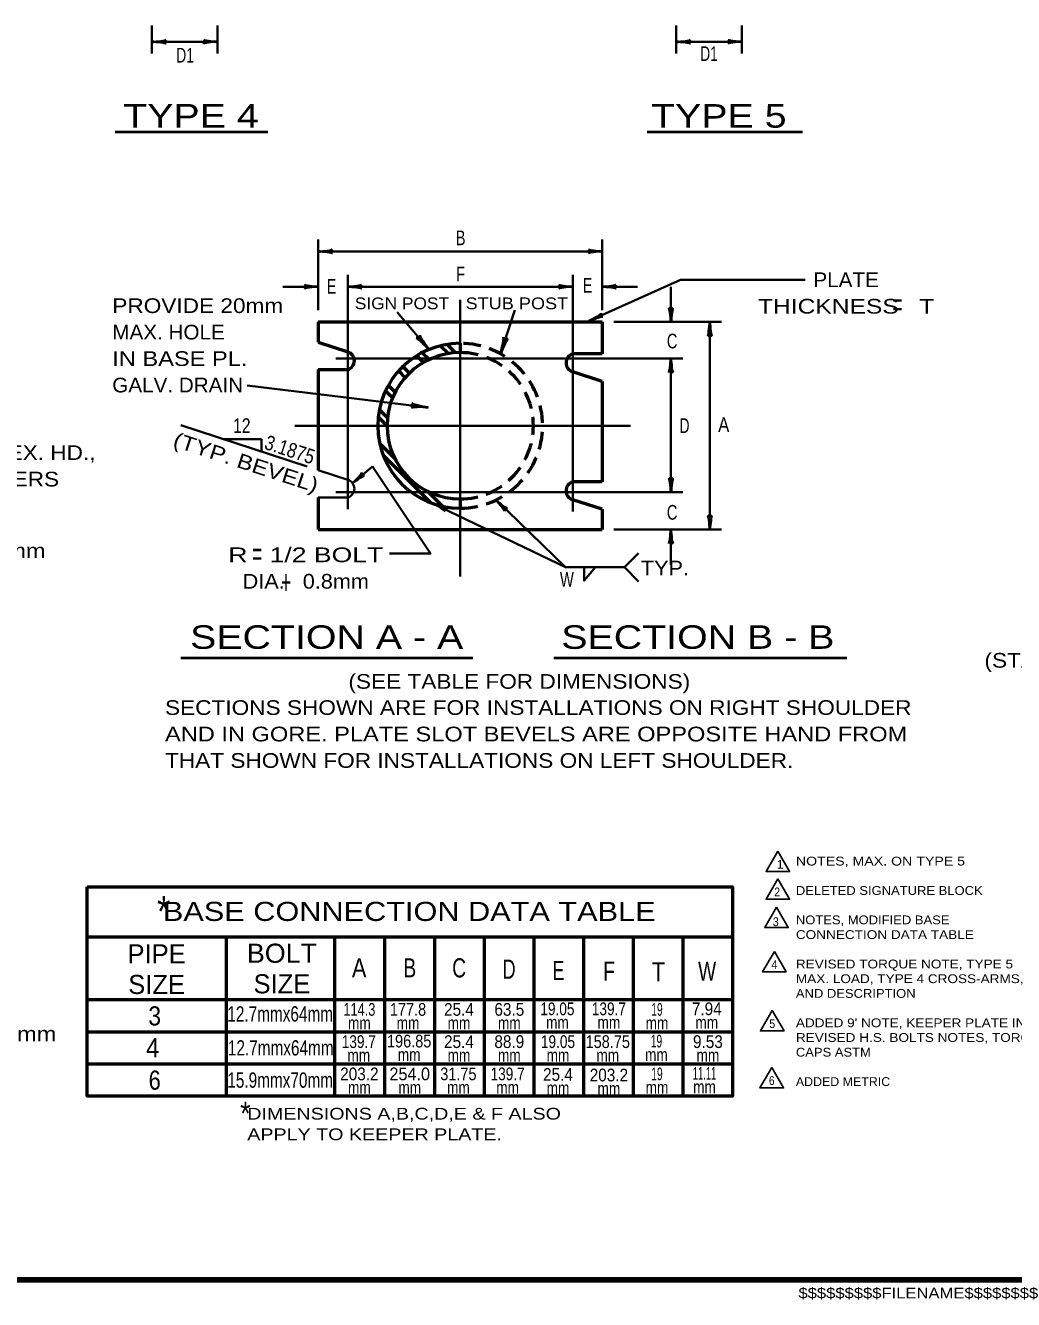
# Model space of a CAD drawing. Extents: x 11 to 867, y -284 to 260.
# Drawn here: x 429.3 to 630.9, y -276.1 to -16.1 of the extents above; entities that cross this region are included whole.
import ezdxf
from ezdxf.enums import TextEntityAlignment as Align

# ---------------------------------------------------------------- set-up
doc = ezdxf.new("R2010")
doc.units = 0
doc.header["$LTSCALE"] = 1.2
doc.linetypes.add('MEDIUM_DASHED', pattern=[4.5, 3, -1.5])
doc.layers.add('1', color=7, linetype='Continuous', lineweight=53)

msp = doc.modelspace()

# ---------------------------------------------------------------- linework, layer by layer
at = {"layer": '1', "lineweight": 35}
for p, q in [((455.129, -16.126), (455.129, -21.85)), ((468.493, -16.126), (468.493, -21.85)), ((562.089, -16.126), (562.089, -21.85)), ((575.453, -16.126), (575.453, -21.85)), ((455.129, -19.45), (468.493, -19.45)), ((562.089, -19.45), (575.453, -19.45)), ((489.053, -74.235), (489.053, -59.835)), ((489.053, -62.235), (546.969, -62.235)), ((546.969, -74.235), (546.969, -59.835)), ((495.059, -67.035), (495.059, -114.865)), ((540.963, -67.035), (540.963, -115.303)), ((489.053, -69.435), (481.853, -69.435)), ((495.059, -69.435), (540.963, -69.435)), ((544.347, -76.403), (562.932, -68.008)), ((546.969, -69.435), (554.169, -69.435)), ((560.995, -76.635), (560.995, -69.435)), ((562.932, -68.008), (588.379, -68.008)), ((518.011, -72.1), (518.011, -80.99)), ((511.632, -82.246), (505.183, -74.636)), ((526.246, -83.144), (529.131, -74.233)), ((549.369, -76.635), (571.331, -76.635)), ((568.931, -76.635), (568.931, -118.985)), ((518.011, -82.881), (518.011, -112.738)), ((492.659, -84.073), (563.395, -84.073)), ((560.995, -84.073), (560.995, -111.367)), ((511.477, -94.083), (474.575, -89.585)), ((461.003, -97.706), (486.771, -106.125)), ((484.253, -97.809), (552.737, -97.809)), ((496.073, -109.555), (500.099, -106.095)), ((489.053, -106.867), (495.059, -108.831)), ((492.659, -111.367), (563.395, -111.367)), ((489.053, -112.465), (495.059, -112.465)), ((518.011, -114.629), (518.011, -128.585)), ((549.369, -118.985), (571.331, -118.985)), ((560.995, -118.985), (560.995, -126.185)), ((551.509, -126.693), (554.407, -129.591))]:
    msp.add_line(p, q, dxfattribs=at)
at = {"layer": '1', "lineweight": 40}
for p, q in [((447.655, -37.837), (478.743, -37.837)), ((556.154, -37.837), (587.864, -37.837)), ((461.03, -145.139), (520.582, -145.139)), ((537.136, -145.139), (596.878, -145.139))]:
    msp.add_line(p, q, dxfattribs=at)
at = {"layer": '1'}
for p, q in [((489.053, -76.635), (546.969, -76.635)), ((489.053, -76.635), (489.053, -80.755)), ((546.969, -76.635), (546.969, -83.155)), ((489.053, -80.755), (495.059, -82.717)), ((511.66, -84.312), (510.247, -82.899)), ((515.531, -83.092), (513.94, -81.501)), ((517.055, -82.919), (515.35, -81.214)), ((518.011, -80.99), (518.011, -82.881)), ((546.969, -83.155), (540.963, -83.155)), ((507.644, -87.084), (506.306, -85.746)), ((510.546, -84.895), (509.165, -83.514)), ((489.053, -86.351), (495.059, -86.351)), ((489.053, -86.351), (489.053, -106.867)), ((506.815, -87.952), (505.476, -86.613)), ((546.969, -88.751), (540.963, -86.789)), ((504.212, -92.137), (502.779, -90.704)), ((504.749, -90.978), (503.354, -89.583)), ((546.969, -88.751), (546.969, -109.269)), ((503.094, -97.807), (501.296, -96.01)), ((503.178, -96.195), (501.524, -94.54)), ((504.66, -104.465), (501.577, -101.382)), ((512.014, -113.516), (502.294, -103.796)), ((514.432, -114.237), (511.354, -111.159)), ((546.969, -109.269), (540.963, -109.269)), ((489.053, -112.465), (489.053, -118.985)), ((518.011, -112.738), (518.011, -114.629)), ((546.969, -114.865), (540.963, -112.903)), ((546.969, -114.865), (546.969, -118.985)), ((489.053, -118.985), (546.969, -118.985)), ((470.311, -234.638), (470.311, -202.19)), ((502.601, -202.19), (502.601, -234.638)), ((512.736, -202.19), (512.736, -234.638)), ((522.873, -202.19), (522.873, -234.638)), ((533.008, -202.19), (533.008, -234.638)), ((543.145, -202.19), (543.145, -234.638)), ((553.28, -202.19), (553.28, -234.638)), ((563.415, -202.19), (563.415, -234.638)), ((573.55, -214.982), (441.919, -214.982)), ((573.55, -221.534), (441.919, -221.534)), ((573.55, -228.086), (441.919, -228.086))]:
    msp.add_line(p, q, dxfattribs=at)
at = {"layer": '1', "lineweight": 158}
msp.add_line((860.008, -272.101), (68.408, -272.101), dxfattribs=at)
at = {"layer": '1', "lineweight": 35}
for points in [[(477.463, -103.083), (477.463, -100.551), (469.711, -100.551)], [(500.099, -106.095), (511.984, -123.903), (503.564, -123.903)], [(512.583, -113.729), (539.487, -126.693), (525.317, -112.959)], [(539.487, -126.693), (551.509, -126.693), (554.407, -123.795)], [(543.297, -126.693), (543.297, -129.413), (545.581, -126.693)]]:
    msp.add_lwpolyline(points, dxfattribs=at)
at = {"layer": '1', "lineweight": 25}
for points in [[(582.811, -184.624), (580.411, -188.781), (585.211, -188.781)], [(582.811, -190.271), (580.411, -194.428), (585.211, -194.428)], [(582.529, -196.058), (580.129, -200.215), (584.929, -200.215)], [(582.1, -205.114), (579.7, -209.271), (584.5, -209.271)], [(581.66, -217.137), (579.26, -221.294), (584.06, -221.294)], [(581.559, -228.769), (579.159, -232.925), (583.959, -232.925)]]:
    msp.add_lwpolyline(points, close=True, dxfattribs=at)
at = {"layer": '1'}
msp.add_lwpolyline([(441.919, -191.894), (573.55, -191.894), (573.55, -234.638), (441.919, -234.638)], close=True, dxfattribs=at)
for points in [[(492.463, -234.638), (492.463, -202.19), (441.919, -202.19)], [(533.008, -202.19), (512.736, -202.19), (492.463, -202.19)], [(573.55, -202.19), (553.28, -202.19), (533.008, -202.19)]]:
    msp.add_lwpolyline(points, dxfattribs=at)
for centre, radius, start, end in [((494.525, -84.534), 1.894, 286.36876, 73.63124), ((518.011, -97.809), 16.819, 90, 270), ((518.011, -97.809), 14.929, 90, 270), ((541.496, -84.972), 1.894, 106.36876, 253.63124), ((541.496, -111.086), 1.894, 106.36876, 253.63124)]:
    msp.add_arc(centre, radius, start, end, dxfattribs=at)
at = {"layer": '1', "linetype": 'MEDIUM_DASHED'}
for radius in [16.819, 14.929]:
    msp.add_arc((518.011, -97.809), radius, 270, 90, dxfattribs=at)
at = {"layer": '1', "lineweight": 35}
msp.add_arc((494.525, -110.648), 1.894, 286.36876, 73.63124, dxfattribs=at)
at = {"layer": '1', "lineweight": 40}
for centre, major_axis, ratio, start_param, end_param in [((456.249, -19.661), (-1.756, 0.176), 0.07063, 3.1407148, 5.41811), ((456.249, -19.661), (-1.756, 0.176), 0.07063, 3.1407148, 5.41811), ((456.22, -19.173), (-1.786, -0.156), 0.122415, 0.8963533, 3.1415927), ((456.22, -19.173), (-1.786, -0.156), 0.122415, 0.8963533, 3.1415927), ((467.402, -19.726), (1.786, 0.156), 0.122415, 0.8963533, 3.1415927), ((467.372, -19.238), (1.756, -0.176), 0.07063, 3.1407148, 5.41811), ((563.209, -19.661), (-1.756, 0.176), 0.07063, 3.1407148, 5.41811), ((563.209, -19.661), (-1.756, 0.176), 0.07063, 3.1407148, 5.41811), ((563.18, -19.173), (-1.786, -0.156), 0.122415, 0.8963533, 3.1415927), ((563.18, -19.173), (-1.786, -0.156), 0.122415, 0.8963533, 3.1415927), ((574.362, -19.726), (1.786, 0.156), 0.122415, 0.8963533, 3.1415927), ((574.332, -19.238), (1.756, -0.176), 0.07063, 3.1407148, 5.41811), ((490.173, -62.447), (-1.756, 0.176), 0.07063, 3.1407148, 5.41811), ((490.173, -62.447), (-1.756, 0.176), 0.07063, 3.1407148, 5.41811), ((490.144, -61.959), (-1.786, -0.156), 0.122415, 0.8963533, 3.1415927), ((490.144, -61.959), (-1.786, -0.156), 0.122415, 0.8963533, 3.1415927), ((545.878, -62.512), (1.786, 0.156), 0.122415, 0.8963533, 3.1415927), ((545.848, -62.024), (1.756, -0.176), 0.07063, 3.1407148, 5.41811), ((487.962, -69.712), (1.786, 0.156), 0.122415, 0.8963533, 3.1415927), ((487.932, -69.224), (1.756, -0.176), 0.07063, 3.1407148, 5.41811), ((496.179, -69.647), (-1.756, 0.176), 0.07063, 3.1407148, 5.41811), ((496.15, -69.159), (-1.786, -0.156), 0.122415, 0.8963533, 3.1415927), ((539.871, -69.712), (1.786, 0.156), 0.122415, 0.8963533, 3.1415927), ((539.842, -69.224), (1.756, -0.176), 0.07063, 3.1407148, 5.41811), ((548.089, -69.647), (-1.756, 0.176), 0.07063, 3.1407148, 5.41811), ((548.06, -69.159), (-1.786, -0.156), 0.122415, 0.8963533, 3.1415927), ((545.227, -75.702), (-1.563, -0.877), 0.122415, 0.8963533, 3.1415927), ((560.718, -75.544), (0.156, -1.786), 0.122415, 0.8963533, 3.1415927), ((560.718, -75.544), (0.156, -1.786), 0.122415, 0.8963533, 3.1415927), ((561.206, -75.515), (-0.176, -1.756), 0.07063, 3.1407148, 5.41811), ((561.206, -75.515), (-0.176, -1.756), 0.07063, 3.1407148, 5.41811), ((545.455, -76.135), (-1.673, -0.563), 0.07063, 3.1407148, 5.41811), ((568.719, -77.756), (0.176, 1.756), 0.07063, 3.1407148, 5.41811), ((569.207, -77.727), (-0.156, 1.786), 0.122415, 0.8963533, 3.1415927), ((510.533, -81.462), (1.528, -1.514), 0.122415, 0.8963533, 3.1415927), ((510.533, -81.462), (1.528, -1.514), 0.122415, 0.8963533, 3.1415927), ((510.957, -81.057), (1.202, -1.744), 0.07063, 3.1407148, 5.41811), ((510.957, -81.057), (1.202, -1.744), 0.07063, 3.1407148, 5.41811), ((526.334, -81.796), (-0.482, -2.096), 0.122415, 0.8963533, 3.1415927), ((526.902, -81.943), (-0.85, -1.94), 0.07063, 3.1407148, 5.41811), ((560.783, -85.194), (0.176, 1.756), 0.07063, 3.1407148, 5.41811), ((560.783, -85.194), (0.176, 1.756), 0.07063, 3.1407148, 5.41811), ((561.271, -85.165), (-0.156, 1.786), 0.122415, 0.8963533, 3.1415927), ((561.271, -85.165), (-0.156, 1.786), 0.122415, 0.8963533, 3.1415927), ((510.173, -93.669), (2.067, -0.464), 0.07063, 3.1407148, 5.41811), ((510.137, -94.254), (2.15, -0.073), 0.122415, 0.8963533, 3.1415927), ((496.72, -108.635), (-1.253, -1.282), 0.122415, 0.8963533, 3.1415927), ((497.06, -108.986), (-1.447, -1.012), 0.07063, 3.1407148, 5.41811), ((560.718, -110.276), (0.156, -1.786), 0.122415, 0.8963533, 3.1415927), ((560.718, -110.276), (0.156, -1.786), 0.122415, 0.8963533, 3.1415927), ((561.206, -110.247), (-0.176, -1.756), 0.07063, 3.1407148, 5.41811), ((561.206, -110.247), (-0.176, -1.756), 0.07063, 3.1407148, 5.41811), ((513.5, -114.406), (-1.506, 0.921), 0.07063, 3.1407148, 5.41811), ((513.5, -114.406), (-1.506, 0.921), 0.07063, 3.1407148, 5.41811), ((513.686, -113.954), (-1.676, 0.634), 0.122415, 0.8963533, 3.1415927), ((513.686, -113.954), (-1.676, 0.634), 0.122415, 0.8963533, 3.1415927), ((525.974, -113.891), (-1.139, 1.349), 0.07063, 3.1407148, 5.41811), ((526.293, -113.52), (-1.391, 1.131), 0.122415, 0.8963533, 3.1415927), ((568.654, -117.894), (0.156, -1.786), 0.122415, 0.8963533, 3.1415927), ((568.654, -117.894), (0.156, -1.786), 0.122415, 0.8963533, 3.1415927), ((569.142, -117.865), (-0.176, -1.756), 0.07063, 3.1407148, 5.41811), ((569.142, -117.865), (-0.176, -1.756), 0.07063, 3.1407148, 5.41811), ((560.783, -120.106), (0.176, 1.756), 0.07063, 3.1407148, 5.41811), ((560.783, -120.106), (0.176, 1.756), 0.07063, 3.1407148, 5.41811), ((561.271, -120.077), (-0.156, 1.786), 0.122415, 0.8963533, 3.1415927), ((561.271, -120.077), (-0.156, 1.786), 0.122415, 0.8963533, 3.1415927)]:
    msp.add_ellipse(centre, major_axis=major_axis, ratio=ratio, start_param=start_param, end_param=end_param, dxfattribs=at)

# ---------------------------------------------------------------- texts
at = {"layer": '1'}
for s, height, width, p in [('D1', 3, 0.7, (461.893, -23.694)), ('D1', 3, 0.7, (568.763, -23.365)), ('TYPE 4', 4.8, 1.25, (463.088, -36.947)), ('TYPE 5', 4.8, 1.25, (570.76, -36.98)), ('B', 3, 0.75, (518.089, -60.965)), ('F', 3, 0.75, (518.089, -68.335)), ('PLATE', 3, 1.05, (596.731, -69.524)), ('E', 3, 0.7, (491.775, -70.862)), ('E', 3, 0.7, (543.982, -70.651)), ('SIGN POST', 2.4, 1.1, (506.127, -74.037)), ('STUB POST', 2.4, 1.15, (529.572, -74.037)), ('THICKNESS   T', 3, 1.25, (596.731, -74.924)), ('=', 4.8, 0.55, (607.203, -75.423)), ('C', 3, 0.75, (561.244, -82.023)), ('A', 3, 0.85, (571.77, -99.08)), ('12', 3, 0.8, (473.46, -99.291)), ('D', 3, 0.7, (563.77, -99.291)), ('C', 3, 0.75, (561.244, -116.979)), ('GALV. STEEL 0.9mm', 3, 1.2, (410.019, -124.818)), ('R   1/2 BOLT', 3, 1.35, (486.512, -125.651)), ('=', 4.8, 0.55, (476.617, -126.324)), ('TYP.', 3, 1.1, (559.77, -128.351)), ('DIA.   0.8mm', 3, 1.1, (486.512, -131.051)), ('+', 4.8, 0.55, (482.501, -132.115)), ('W', 3, 0.75, (539.772, -130.667)), ('SECTION A - A', 4.8, 1.25, (490.77, -143.336)), ('SECTION B - B', 4.8, 1.25, (566.489, -143.336)), ('(STAINLESS STEEL BANDING)', 3, 1.15, (658.278, -147.182)), ('(SEE TABLE FOR DIMENSIONS)', 3, 1.15, (530.07, -151.486)), ('2', 1.8, 0.9, (582.67, -193.853)), ('*', 6.24, 0.85, (457.554, -200.029)), ('  BASE CONNECTION DATA TABLE', 3.9, 1.2, (505.878, -198.867)), ('3', 1.8, 0.9, (582.387, -199.923)), ('BOLT', 3.9, 1.05, (481.647, -207.403)), ('A', 3.9, 0.85, (497.404, -210.391)), ('B', 3.9, 0.75, (507.732, -210.391)), ('C', 3.9, 0.75, (517.796, -210.391)), ('D', 3.9, 0.7, (527.992, -210.655)), ('E', 3.9, 0.7, (538.055, -210.92)), ('F', 3.9, 0.75, (548.383, -211.053)), ('T', 3.9, 0.85, (558.447, -211.185)), ('W', 3.9, 0.75, (568.378, -211.053)), ('4', 1.8, 0.95, (582.1, -208.696)), ('114.3', 2.6, 0.75, (497.445, -218.219)), ('177.8', 2.6, 0.85, (507.37, -218.219)), ('25.4', 2.6, 0.9, (517.758, -218.219)), ('63.5', 2.6, 0.9, (528.029, -218.219)), ('19.05', 2.6, 0.8, (537.839, -218.103)), ('139.7', 2.6, 0.8, (548.341, -218.103)), ('19', 2.6, 0.6, (558.152, -218.219)), ('7.94', 2.6, 0.9, (568.308, -218.103)), ('3', 3.9, 0.9, (455.693, -220.192)), ('12.7mmx64mm', 3.12, 0.75, (481.288, -219.398)), ('45mm', 3, 1.2, (428.953, -223.416)), ('mm', 2.6, 0.8, (497.445, -220.981)), ('mm', 2.6, 0.8, (507.37, -220.981)), ('mm', 2.6, 0.8, (517.757, -220.981)), ('mm', 2.6, 0.8, (528.029, -220.981)), ('mm', 2.6, 0.8, (537.839, -220.866)), ('mm', 2.6, 0.8, (548.342, -220.866)), ('mm', 2.6, 0.8, (558.151, -220.981)), ('mm', 2.6, 0.8, (568.308, -220.866)), ('5', 1.8, 0.9, (581.66, -220.719)), ('4', 3.9, 0.95, (455.296, -226.683)), ('12.7mmx64mm', 3.12, 0.75, (481.403, -226.324)), ('139.7', 2.6, 0.8, (497.33, -224.799)), ('196.85', 2.6, 0.85, (507.601, -224.683)), ('25.4', 2.6, 0.9, (517.758, -224.799)), ('88.9', 2.6, 0.9, (528.029, -224.799)), ('19.05', 2.6, 0.8, (537.955, -224.799)), ('158.75', 2.6, 0.85, (548.111, -224.799)), ('19', 2.6, 0.6, (558.036, -224.683)), ('9.53', 2.6, 0.9, (568.539, -224.799)), ('mm', 2.6, 0.8, (497.33, -227.561)), ('mm', 2.6, 0.8, (507.601, -227.446)), ('mm', 2.6, 0.8, (517.757, -227.561)), ('mm', 2.6, 0.8, (528.029, -227.561)), ('mm', 2.6, 0.8, (537.954, -227.561)), ('mm', 2.6, 0.8, (548.111, -227.561)), ('mm', 2.6, 0.8, (558.036, -227.446)), ('mm', 2.6, 0.8, (568.539, -227.561)), ('203.2', 2.6, 0.9, (497.445, -231.379)), ('254.0', 2.6, 0.95, (507.717, -231.379)), ('31.75', 2.6, 0.85, (517.642, -231.379)), ('139.7', 2.6, 0.8, (527.683, -231.379)), ('19', 2.6, 0.6, (558.152, -231.379)), ('11.11', 2.6, 0.55, (567.846, -231.263)), ('6', 3.9, 0.85, (455.693, -233.306)), ('15.9mmx70mm', 3.12, 0.75, (481.288, -232.905)), ('25.4', 2.6, 0.9, (537.955, -231.494)), ('203.2', 2.6, 0.9, (548.342, -231.609)), ('6', 1.8, 0.85, (581.559, -232.351)), ('mm', 2.6, 0.8, (497.445, -234.141)), ('mm', 2.6, 0.8, (507.717, -234.141)), ('mm', 2.6, 0.8, (517.642, -234.141)), ('mm', 2.6, 0.8, (527.683, -234.141)), ('mm', 2.6, 0.8, (537.955, -234.257)), ('mm', 2.6, 0.8, (548.342, -234.372)), ('mm', 2.6, 0.8, (558.151, -234.141)), ('mm', 2.6, 0.8, (567.846, -234.026)), ('*', 4.8, 0.85, (474.194, -240.529))]:
    msp.add_text(s, height=height, dxfattribs=dict(at, width=width)).set_placement(p, align=Align.CENTER)
for s, height, width, p in [('PROVIDE 20mm', 3, 1.15, (447.045, -74.807)), ('MAX. HOLE', 3, 1.05, (447.045, -80.207)), ('IN BASE PL.', 3, 1.2, (447.045, -85.607)), ('GALV. DRAIN', 3, 1.05, (447.045, -91.007)), ('H.S. BOLT WITH HEX. HD.,', 3, 1.15, (385.698, -104.799)), ('HEX. NUT & WASHERS', 3, 1.15, (385.698, -110.199)), ('SECTIONS SHOWN ARE FOR INSTALLATIONS ON RIGHT SHOULDER', 3, 1.15, (457.8, -156.823)), ('AND IN GORE. PLATE SLOT BEVELS ARE OPPOSITE HAND FROM', 3, 1.2, (457.8, -162.223)), ('THAT SHOWN FOR INSTALLATIONS ON LEFT SHOULDER.', 3, 1.15, (457.8, -167.623)), ('NOTES, MAX. ON TYPE 5', 1.8, 1.2, (586.48, -187.554)), ('DELETED SIGNATURE BLOCK', 1.8, 1.1, (586.48, -193.554)), ('NOTES, MODIFIED BASE', 1.8, 1.1, (586.48, -199.554)), ('CONNECTION DATA TABLE', 1.8, 1.15, (586.48, -202.554)), ('REVISED TORQUE NOTE, TYPE 5', 1.8, 1.15, (586.48, -208.554)), ('MAX. LOAD, TYPE 4 CROSS-ARMS,', 1.8, 1.15, (586.48, -211.554)), ('AND DESCRIPTION', 1.8, 1.1, (586.48, -214.554)), ("ADDED 9' NOTE, KEEPER PLATE INFO.,", 1.8, 1.15, (586.48, -220.554)), ('REVISED H.S. BOLTS NOTES, TORQUE,', 1.8, 1.15, (586.48, -223.554)), ('CAPS ASTM', 1.8, 1.1, (586.48, -226.554)), ('ADDED METRIC', 1.8, 1.05, (586.48, -232.554)), ('  DIMENSIONS A,B,C,D,E & F ALSO', 2.4, 1.25, (472.351, -239.406)), ('  APPLY TO KEEPER PLATE.', 2.4, 1.25, (472.351, -243.606)), ('$$$$$$$$$FILENAME$$$$$$$$', 2.2, 1.15, (587.008, -275.901))]:
    msp.add_text(s, height=height, dxfattribs=dict(at, width=width)).set_placement(p)
for s, width, p in [('(TYP. BEVEL)', 1.2, (473.84, -106.718)), ('3.1875', 0.85, (482.808, -104.097))]:
    msp.add_text(s, height=3, rotation=341.906, dxfattribs=dict(at, width=width)).set_placement(p, align=Align.CENTER)
for s, height, p in [('1', 1.8, (583.273, -188.206)), ('PIPE', 3.9, (456.09, -207.535)), ('SIZE', 3.9, (456.09, -213.775)), ('SIZE', 3.9, (481.647, -213.643))]:
    msp.add_text(s, height=height, dxfattribs=at).set_placement(p, align=Align.CENTER)

doc.saveas('drawing.dxf')
